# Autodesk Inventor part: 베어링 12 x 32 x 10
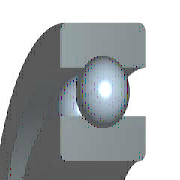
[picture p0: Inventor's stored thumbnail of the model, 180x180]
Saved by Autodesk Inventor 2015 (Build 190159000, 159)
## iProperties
IsCustomPart: 1
Created: 2012-02
Part Number: 베어링 12 x 32 x 10
Material: 강철, 연강
Description: 깊은 그루브 볼 베어링
Document SubType Name: Modeling
Standard: KS B 2023
Designer: test
Standards Organization: KS
Language: ko-KR
Size Designation: 6201 - 12 x 32 x 10
Categories: <MemberInstance><Categories><Category DisplayName="샤프트 부품" InternalName="7f7aeb1f-a693-4053-b835-cee3144e0d98" Mnemonic="SHFT"><Category DisplayName="베어링" Inter
Density: 1 g/cm^3
Appearance: 노란색
Author: test
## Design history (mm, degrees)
sketch "스케치" dims "d0" = 5.2 (= -0.26 x WD + 0.26 x BD)
  geometry: L1 (2.4, 11)-(7.6, 11); L2 (5, 11)-(5, 8.4); L3 (5, 11)-(5, 13.6); L4 (3.068, 9.26)-(0, 9.26); L5 (0, 6)-(10, 6); L6 (3.068, 12.74)-(0, 12.74); L7 (0, 16)-(10, 16); L8 (10, 6)-(10, 9.26); L9 (6.932, 9.26)-(10, 9.26); L10 (6.932, 12.74)-(10, 12.74); L11 (10, 16)-(10, 12.74); L12 (-1.4, 0)-(8.4, 0) reference; L13 (0, -0.3)-(0, 5.3) reference
  constraints: 22 end point, 4 point on line, 2 collinear, 2 perpendicular, 2 symmetric about line, 1 midpoint, 1 parallel, 14 other
  dimensions: "d9" = 12 diameter of L5 L12 (= WD); "d11" = 32 diameter of L7 L12 (= BD); "d12" = 10 distance between parallel lines of L8 L13 (= KB); "d13" = 18.52 diameter of L9 L12 (= 0.326 x BD + 0.674 x WD)
revolve "본체" stored, may be unused: angle "d6" = 90 deg
revolve "볼" stored, may be unused: angle "d7" = 90 deg
pattern_circular "IDS_ARRAYBALL[SIMPL:T]" dims angle "d3" = 360 deg
body "Solid1"
fillet "모깎기1" dims "d1" = 0.6 (= KRS)
other parameters: "WD" = 12 [user parameter; used in 5 equation terms], "BD" = 32 [user parameter; used in 5 equation terms], "KB" = 10 [user parameter; used in 1 equation term], "KRS" = 0.6 [user parameter; used in 1 equation term], "d4" = 0, "d5" = 0, "d8" = 0, "d14" = 0, "d15" = 0, "BBA" = 0 [user parameter], "BC0" = 3100000 [user parameter], "BC" = 6890000 [user parameter], "BR" = 16 (= 0.5 x BD) [user parameter], "WR" = 6 (= 0.5 x WD) [user parameter]
